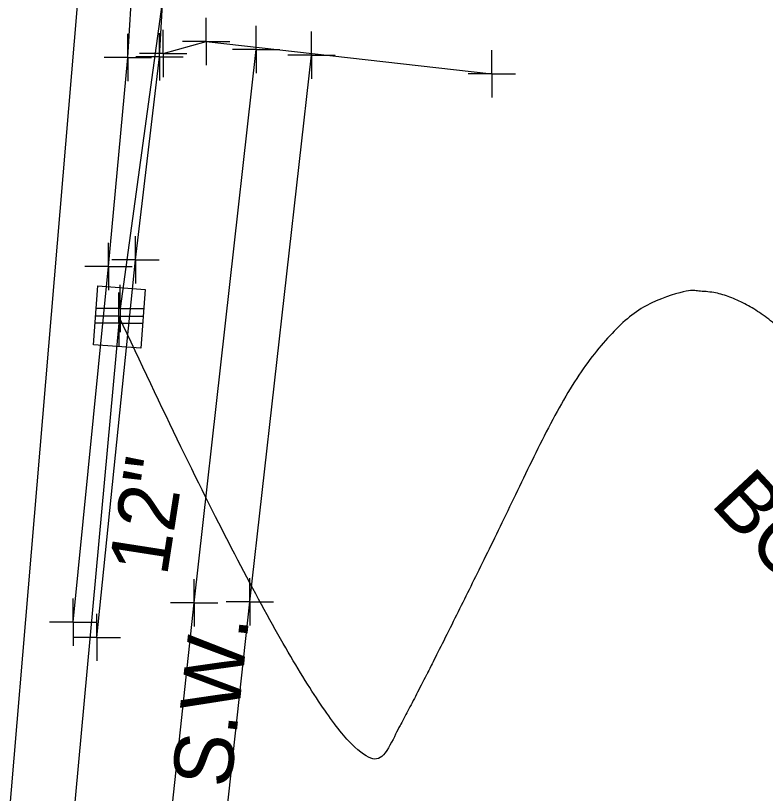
# Model space of a CAD drawing. Extents: x 0 to 1944463, y 0 to 420651.
# Drawn here: x 1942706.1 to 1942769.5, y 417567.2 to 417633 of the extents above; entities that cross this region are included whole.
import ezdxf

# ---------------------------------------------------------------- set-up
doc = ezdxf.new("R2010")
doc.units = 0
for name, color, linetype in [('SUR - DRG - Storm Sewer', 7, 'Continuous'), ('SUR - DRG - Storm Sewer - Points - Locators', 7, 'Continuous'), ('SUR - DRG - Storm Sewer Text', 7, 'Continuous'), ('SUR - PROPERTY - Property Lines', 7, 'Continuous'), ('SUR - TRAN - Features', 7, 'Continuous'), ('SUR - TRAN - Features - Points - Locators', 7, 'Continuous'), ('SUR - TRAN - Features Text', 7, 'Continuous'), ('SUR - TRAN - Roads', 7, 'Continuous'), ('SUR - UTL - Water', 7, 'Continuous')]:
    doc.layers.add(name, color=color, linetype=linetype)

msp = doc.modelspace()

# ---------------------------------------------------------------- linework, layer by layer
at = {"layer": 'SUR - DRG - Storm Sewer'}
msp.add_line((1942714.851, 417607.506), (1942714.851, 417607.506), dxfattribs=at)
for points in [[(1942728.728, 417709.023), (1942714.924, 417608.23)], [(1942713.036, 417610.143), (1942717.025, 417609.855), (1942716.666, 417604.869), (1942712.677, 417605.156), (1942713.036, 417610.143)], [(1942714.799, 417606.991), (1942710.896, 417564.354)]]:
    msp.add_lwpolyline(points, dxfattribs=at)
at = {"layer": 'SUR - DRG - Storm Sewer - Points - Locators'}
for p, q in [((1942714.924, 417608.23), (1942714.924, 417610.23)), ((1942714.819, 417607.596), (1942714.819, 417609.596)), ((1942714.799, 417606.991), (1942714.799, 417608.991)), ((1942714.924, 417608.23), (1942712.924, 417608.23)), ((1942714.924, 417608.23), (1942716.924, 417608.23)), ((1942714.924, 417608.23), (1942714.924, 417606.23)), ((1942714.819, 417607.596), (1942712.819, 417607.596)), ((1942714.819, 417607.596), (1942716.819, 417607.596)), ((1942714.819, 417607.596), (1942714.819, 417605.596)), ((1942714.799, 417606.991), (1942712.799, 417606.991)), ((1942714.799, 417606.991), (1942716.799, 417606.991)), ((1942714.799, 417606.991), (1942714.799, 417604.991))]:
    msp.add_line(p, q, dxfattribs=at)
at = {"layer": 'SUR - DRG - Storm Sewer Text'}
msp.add_open_spline([(1942772.474, 417604.822), (1942760.538, 417617.684), (1942740.338, 417575.883), (1942734.37, 417565.547), (1942714.851, 417607.506)], degree=2, dxfattribs=at)
at = {"layer": 'SUR - PROPERTY - Property Lines'}
for p, q in [((1942715.579, 417629.468), (1942715.579, 417631.468)), ((1942715.579, 417629.468), (1942713.579, 417629.468)), ((1942715.579, 417629.468), (1942717.579, 417629.468)), ((1942715.579, 417629.468), (1942715.579, 417627.468)), ((1942713.936, 417611.778), (1942713.936, 417613.778)), ((1942713.936, 417611.778), (1942711.936, 417611.778)), ((1942713.936, 417611.778), (1942715.936, 417611.778)), ((1942713.936, 417611.778), (1942713.936, 417609.778)), ((1942710.949, 417581.708), (1942710.949, 417583.708)), ((1942710.949, 417581.708), (1942708.949, 417581.708)), ((1942710.949, 417581.708), (1942712.949, 417581.708)), ((1942710.949, 417581.708), (1942710.949, 417579.708))]:
    msp.add_line(p, q, dxfattribs=at)
at = {"layer": 'SUR - TRAN - Features'}
for points in [[(1942712.955, 417580.431), (1942716.233, 417612.361), (1942718.248, 417629.53), (1942720.549, 417669.944)], [(1942718.55, 417629.792), (1942722.198, 417630.811), (1942746.352, 417628.081)], [(1942716.163, 417536.72), (1942721.186, 417583.355), (1942726.435, 417630.128)], [(1942720.73, 417536.201), (1942725.889, 417583.435), (1942731.1, 417629.664)]]:
    msp.add_lwpolyline(points, dxfattribs=at)
at = {"layer": 'SUR - TRAN - Features - Points - Locators'}
for p, q in [((1942722.198, 417630.811), (1942722.198, 417632.811)), ((1942726.435, 417630.128), (1942726.435, 417632.128)), ((1942718.248, 417629.53), (1942718.248, 417631.53)), ((1942718.55, 417629.792), (1942718.55, 417631.792)), ((1942731.1, 417629.664), (1942731.1, 417631.664)), ((1942722.198, 417630.811), (1942720.198, 417630.811)), ((1942722.198, 417630.811), (1942724.198, 417630.811)), ((1942722.198, 417630.811), (1942722.198, 417628.811)), ((1942726.435, 417630.128), (1942724.435, 417630.128)), ((1942726.435, 417630.128), (1942728.435, 417630.128)), ((1942726.435, 417630.128), (1942726.435, 417628.128)), ((1942718.248, 417629.53), (1942716.248, 417629.53)), ((1942718.55, 417629.792), (1942716.55, 417629.792)), ((1942718.248, 417629.53), (1942720.248, 417629.53)), ((1942718.248, 417629.53), (1942718.248, 417627.53)), ((1942718.55, 417629.792), (1942720.55, 417629.792)), ((1942718.55, 417629.792), (1942718.55, 417627.792)), ((1942731.1, 417629.664), (1942729.1, 417629.664)), ((1942731.1, 417629.664), (1942733.1, 417629.664)), ((1942731.1, 417629.664), (1942731.1, 417627.664)), ((1942746.352, 417628.081), (1942746.352, 417630.081)), ((1942746.352, 417628.081), (1942744.352, 417628.081)), ((1942746.352, 417628.081), (1942748.352, 417628.081)), ((1942746.352, 417628.081), (1942746.352, 417626.081)), ((1942716.233, 417612.361), (1942716.233, 417614.361)), ((1942716.233, 417612.361), (1942714.233, 417612.361)), ((1942716.233, 417612.361), (1942718.233, 417612.361)), ((1942716.233, 417612.361), (1942716.233, 417610.361)), ((1942725.889, 417583.435), (1942725.889, 417585.435)), ((1942721.186, 417583.355), (1942721.186, 417585.355)), ((1942725.889, 417583.435), (1942723.889, 417583.435)), ((1942725.889, 417583.435), (1942727.889, 417583.435)), ((1942725.889, 417583.435), (1942725.889, 417581.435)), ((1942721.186, 417583.355), (1942719.186, 417583.355)), ((1942721.186, 417583.355), (1942723.186, 417583.355)), ((1942721.186, 417583.355), (1942721.186, 417581.355)), ((1942712.955, 417580.431), (1942712.955, 417582.431)), ((1942712.955, 417580.431), (1942710.955, 417580.431)), ((1942712.955, 417580.431), (1942714.955, 417580.431)), ((1942712.955, 417580.431), (1942712.955, 417578.431))]:
    msp.add_line(p, q, dxfattribs=at)
at = {"layer": 'SUR - TRAN - Roads'}
msp.add_lwpolyline([(1942710.949, 417581.708), (1942713.936, 417611.778), (1942715.579, 417629.468), (1942718.106, 417670.755), (1942724.769, 417700.99), (1942727.001, 417709.239), (1942735.883, 417740.05)], dxfattribs=at)
at = {"layer": 'SUR - UTL - Water'}
msp.add_lwpolyline([(1942697.198, 417466.364), (1942715.696, 417685.807)], dxfattribs=at)

# ---------------------------------------------------------------- texts
at = {"layer": 'SUR - DRG - Storm Sewer Text'}
for s, height, rotation, p in [('12"', 5, 81.12374, (1942718.875, 417585.517)), ("BOT-1054.01'", 4.99999, 313, (1942764.757, 417591.662))]:
    msp.add_text(s, height=height, rotation=rotation, dxfattribs=at).set_placement(p)
at = {"layer": 'SUR - TRAN - Features Text'}
msp.add_text('S.W.', height=5, rotation=83.76772, dxfattribs=at).set_placement((1942724.261, 417567.619))

doc.saveas('drawing.dxf')
